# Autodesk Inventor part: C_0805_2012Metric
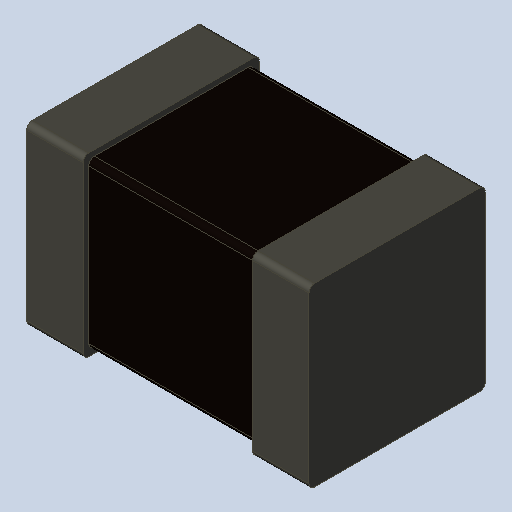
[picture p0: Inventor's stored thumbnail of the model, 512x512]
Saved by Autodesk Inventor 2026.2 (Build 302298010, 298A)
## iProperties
Created: 2026-10
Part Number: C_0805_2012Metric
Material: Générique
Document SubType Name: Modeling
Designer: mel
Density: 1 g/cm^3
Appearance: Par défaut
Author: mel
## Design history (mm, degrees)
feature "Base1"
node "Solide1"
